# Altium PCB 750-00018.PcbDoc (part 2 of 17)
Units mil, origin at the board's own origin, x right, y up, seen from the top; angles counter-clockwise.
Board outline 7086.64 x 6299.21 mil, 8 copper layers (Top Layer, L2, L3, L4, L5, L6, L7, Bottom Layer), stack 60.6 mil thick; 1356 components, 1054 nets, 4851 pads, 4296 vias.
Unrouted connection lines stored in the file: 12.
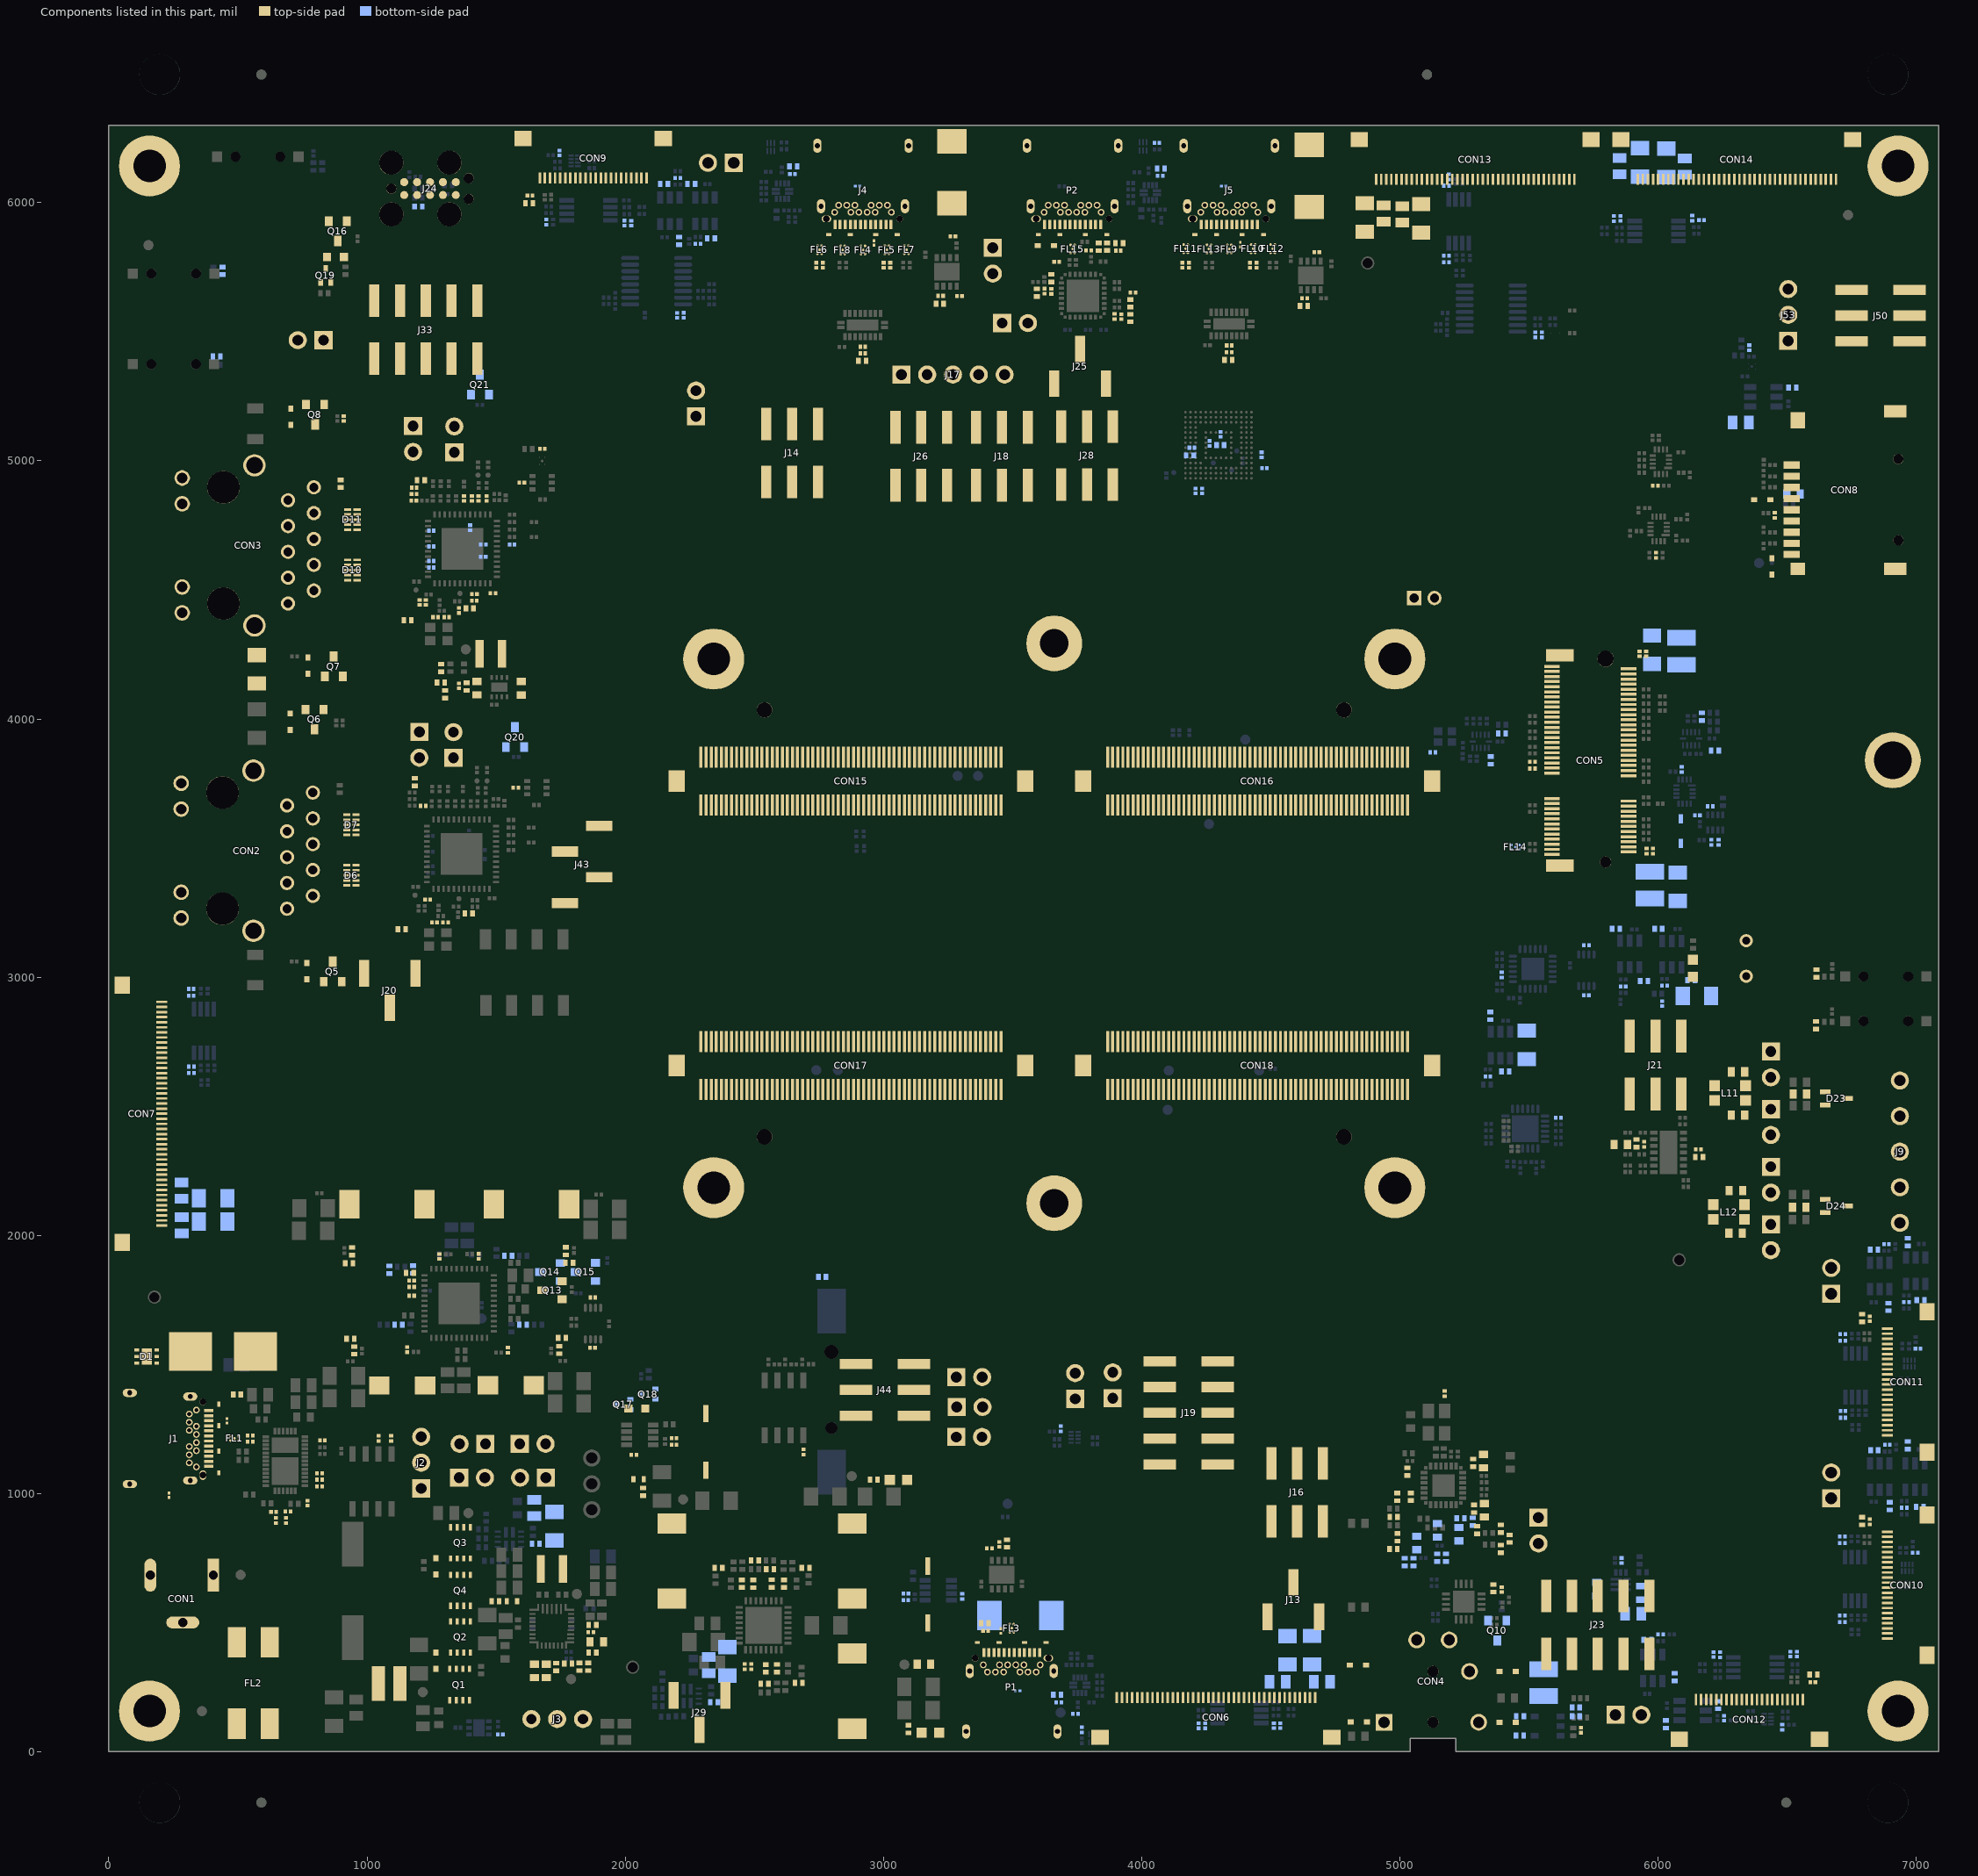
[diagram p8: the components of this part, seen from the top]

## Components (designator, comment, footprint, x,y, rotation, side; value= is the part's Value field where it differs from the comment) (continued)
C142 "0201, 27pF, 25V" "Cap, C0201, Height 0.3mm" 1261.1,3212.51 r180 top value=27pF
C143 "0201, 33pF, 25V" "Cap, C0201, Height 0.3mm" 1304.13,3212.39 r180 top value=33pF
C144 "0201, 1uF, 10V" "Cap, C0201, Height 0.3mm" 1356.39,4420.54 r90 top value=1uF
C145 "0201, 1uF, 10V" "Cap, C0201, Height 0.3mm" 1399.27,4740.79 r90 bottom value=1uF
C146 "0201, 0.1uF, 10V" "Cap, C0201, Height 0.3mm" 1415.53,4457.99 r0 top value=100nF
C147 "0201, 1000pF, 25V" "Cap, C0201, Height 0.3mm" 1449.6,4627.97 r180 bottom value=1000pF
C148 "0201, 100pF, 50V" "Cap, C0201, Height 0.3mm" 1415.74,4483.92 r0 top value=100pF
C149 "0201, 22pF, 50V" "Cap, C0201, Height 0.3mm" 1561.73,4675.3 r180 bottom value=22pF
C150 "0201, 470pF, 25V" "Cap, C0201, Height 0.3mm" 1463.05,4854.3 r90 top value=470pF
C151 "0201, 470pF, 25V" "Cap, C0201, Height 0.3mm" 1431.72,4854.3 r90 top value=470pF
C152 "0201, 1uF, 10V" "Cap, C0201, Height 0.3mm" 1182.19,4896.04 r0 top value=1uF
C153 "0201, 0.1uF, 10V" "Cap, C0201, Height 0.3mm" 1203.49,4451.48 r270 top value=100nF
C154 "0201, 1000pF, 25V" "Cap, C0201, Height 0.3mm" 1182.03,4870.97 r180 top value=1000pF
C155 "0201, 100pF, 50V" "Cap, C0201, Height 0.3mm" 1227.55,4451.46 r270 top value=100pF
C156 "0201, 100pF, 50V" "Cap, C0201, Height 0.3mm" 1181.19,4846.01 r180 top value=100pF
C157 "0201, 1uF, 10V" "Cap, C0201, Height 0.3mm" 1248.68,4729.23 r180 bottom value=1uF
C158 "0201, 1000pF, 25V" "Cap, C0201, Height 0.3mm" 1248.68,4612.08 r0 bottom value=1000pF
C159 "0201, 1000pF, 25V" "Cap, C0201, Height 0.3mm" 1248.68,4586.71 r0 bottom value=1000pF
C160 "0201, 1uF, 10V" "Cap, C0201, Height 0.3mm" 1487.6,4487.51 r180 top value=1uF
C161 "0201, 0.1uF, 10V" "Cap, C0201, Height 0.3mm" 1450.19,4675.31 r180 bottom value=100nF
C162 "0201, 1000pF, 25V" "Cap, C0201, Height 0.3mm" 1406.07,4854.3 r90 top value=1000pF
C163 "0201, 1000pF, 25V" "Cap, C0201, Height 0.3mm" 1248.67,4668.17 r0 bottom value=1000pF
C164 "0402, 220nF, 16V" "Chip. 0402, RF" 897.51,4911.38 r270 top value=220nF
C165 "0201, 10nF, 10V" "Cap, C0201, Height 0.3mm" 1375.37,4854.3 r90 top value=10nF
C166 "1206, 1000pF, 2kV" "CAP, 1206, 1.8mm, HD" 572.62,4192.66 r270 top value=1000pF
C167 "0201, 1uF, 10V" "Cap, C0201, Height 0.3mm" 909.63,5163.77 r90 top value=1uF
C168 "0201, 27pF, 25V" "Cap, C0201, Height 0.3mm" 1265.41,4394.48 r180 top value=27pF
C169 "0201, 33pF, 25V" "Cap, C0201, Height 0.3mm" 1308.07,4394.71 r180 top value=33pF
C170 "7343, 150uF, 16V" "CAP, 7343, Polarized, 2.8mm" 3530.22,527.87 r0 bottom value=150uF
C171 "0201, 0.1uF, 10V" "Cap, C0201, Height 0.3mm" 3395.57,468.29 r180 top value=100nF
C172 "0402, 10uF, 10V" "Chip. 0402, RF" 3479.01,806.58 r270 top value=10uF
C173 "0201, 0.1uF, 10V" "Cap, C0201, Height 0.3mm" 3449.09,803.37 r90 top value=100nF
C174 "0201, 0.1uF, 10V" "Cap, C0201, Height 0.3mm" 3268.73,5868.81 r180 top value=100nF
C175 "7343, 150uF, 16V" "CAP, 7343, Polarized, 2.8mm" 3264.97,6117.56 r90 top value=150uF
C176 "0402, 10uF, 10V" "Chip. 0402, RF" 2650.49,6140.43 r180 bottom value=10uF
C177 "0201, 0.1uF, 10V" "Cap, C0201, Height 0.3mm" 2647.54,6110.74 r0 bottom value=100nF
C178 "0402, 10uF, 10V" "Chip. 0402, RF" 3218.28,5608.48 r0 top value=10uF
C179 "0201, 0.1uF, 10V" "Cap, C0201, Height 0.3mm" 3221.2,5638.83 r180 top value=100nF
C180 "0201, 10nF, 10V" "Cap, C0201, Height 0.3mm" 2919.94,5441.5 r180 top value=10nF
C181 "0201, 0.1uF, 10V" "Cap, C0201, Height 0.3mm" 2920.05,5416.19 r0 top value=100nF
C182 "0402, 10uF, 10V" "Chip. 0402, RF" 2917.95,5387.18 r0 top value=10uF
C183 "0201, 0.1uF, 10V" "Cap, C0201, Height 0.3mm" 4678.08,5808.21 r180 top value=100nF
C184 "7343, 150uF, 16V" "CAP, 7343, Polarized, 2.8mm" 4649.21,6103.61 r90 top value=150uF
C185 "0402, 10uF, 10V" "Chip. 0402, RF" 4074.22,6132.67 r180 bottom value=10uF
C186 "0201, 0.1uF, 10V" "Cap, C0201, Height 0.3mm" 4071.8,6103.5 r0 bottom value=100nF
C187 "0402, 10uF, 10V" "Chip. 0402, RF" 4628.09,5599.47 r0 top value=10uF
C188 "0201, 0.1uF, 10V" "Cap, C0201, Height 0.3mm" 4630.92,5629.62 r180 top value=100nF
C189 "0201, 10nF, 10V" "Cap, C0201, Height 0.3mm" 4338.96,5446.95 r180 top value=10nF
C190 "0201, 0.1uF, 10V" "Cap, C0201, Height 0.3mm" 4338.28,5420.91 r0 top value=100nF
C191 "0402, 10uF, 10V" "Chip. 0402, RF" 4335.77,5390.66 r0 top value=10uF
C192 "0603, 10uF, 25V" "Chip, 0603, RF" 5228.02,842.55 r90 bottom value=10uF
C193 "0402, 100nF, 50V" "Chip. 0402, RF" 5235.12,903.79 r0 bottom value=100nF
C194 "0402, 1.0uF, 16V" "Chip. 0402, RF" 5281.67,891.18 r270 bottom value=1.0uF
C195 "0603, 10uF, 25V" "Chip, 0603, RF" 5326.44,935.66 r90 top value=10uF
C196 "0402, 100nF, 50V" "Chip. 0402, RF" 5286.87,941.36 r270 top value=100nF
C197 "0402, 1.0uF, 16V" "Chip. 0402, RF" 5361.65,633.11 r90 top value=1.0uF
C198 "0201, 0.1uF, 10V" "Cap, C0201, Height 0.3mm" 5394.19,627.98 r90 top value=100nF
C199 "0603, 10uF, 25V" "Chip, 0603, RF" 5323.69,1125.57 r270 top value=10uF
C200 "0402, 100nF, 50V" "Chip. 0402, RF" 5284.51,1119.05 r90 top value=100nF
C201 "0402, 220pF, 50V" "Chip. 0402, RF" 5178.91,751.86 r90 bottom value=220pF
C202 "0603, 47uF, 6.3V" "Chip, 0603, RF" 5144.76,857.54 r270 bottom value=47uF
C203 "0603, 47uF, 6.3V" "Chip, 0603, RF" 5065.31,808.86 r270 bottom value=47uF
C204 "0402, 220pF, 50V" "Chip. 0402, RF" 5017.95,734.9 r270 bottom value=220pF
C205 "1210, 100uF, 16V" "CAP, 1210, 2.8mm" 5556.18,267.56 r270 bottom value=100uF
C206 "0402, 1.0uF, 16V" "Chip. 0402, RF" 5681.57,171.42 r180 bottom value=1.0uF
C207 "0402, 2.2uF, 10V" "Chip. 0402, RF" 5464.98,137.9 r0 bottom value=2.2uF
C208 "0402, 1.0uF, 16V" "Chip. 0402, RF" 5028.45,1084.99 r90 top value=1.0uF
C209 "0402, 15pF, 50V" "Chip. 0402, RF" 4975.85,909.31 r180 top value=15pF
C210 "0402, 100nF, 50V" "Chip. 0402, RF" 5681.57,137.75 r180 bottom value=100nF
C211 "0402, 15pF, 50V" "Chip. 0402, RF" 5390.18,785.59 r270 top value=15pF
C212 "0402, 10uF, 6.3V" "Chip. 0402, RF" 4990.14,987.46 r270 top value=10uF
C213 "0402, 15pF, 50V" "Chip. 0402, RF" 5424.25,825.43 r90 top value=15pF
C214 "0402, 15pF, 50V" "Chip. 0402, RF" 5390.2,864.07 r90 top value=15pF
C215 "0805, 1uF, 50V" "CAP, 0805, 1.45mm, HD" 281.69,2173.6 r90 bottom value=1uF
C216 "1206, 10uF, 50V" "CAP, 1206, 1.8mm, HD" 403.81,2143.68 r0 bottom value=10uF
C217 "0805, 1uF, 50V" "CAP, 0805, 1.45mm, HD" 282.05,2038.71 r270 bottom value=1uF
C218 "1206, 10uF, 50V" "CAP, 1206, 1.8mm, HD" 403.55,2053.43 r0 bottom value=10uF
C219 "0805, 1uF, 50V" "CAP, 0805, 1.45mm, HD" 4526.76,270.5 r180 bottom value=1uF
C220 "0402, 4.7uF, 10V" "Chip. 0402, RF" 6158.69,2303.34 r0 top value=4.7uF
C221 "0402, 4.7uF, 10V" "Chip. 0402, RF" 2762.57,1840.06 r0 bottom value=4.7uF
C222 "0201, 0.1uF, 10V" "Cap, C0201, Height 0.3mm" 5946.16,2352.79 r90 top value=100nF
C223 "0201, 1uF, 10V" "Cap, C0201, Height 0.3mm" 4219.98,100.77 r270 bottom value=1uF
C224 "0201, 1uF, 10V" "Cap, C0201, Height 0.3mm" 5550.11,5488.24 r270 bottom value=1uF
C225 "0201, 1uF, 10V" "Cap, C0201, Height 0.3mm" 4537.13,101.02 r90 bottom value=1uF
C226 "0201, 0.1uF, 10V" "Cap, C0201, Height 0.3mm" 4245.94,100.78 r90 bottom value=100nF
C227 "0201, 0.1uF, 10V" "Cap, C0201, Height 0.3mm" 5524.13,5488.23 r90 bottom value=100nF
C228 "0201, 0.1uF, 10V" "Cap, C0201, Height 0.3mm" 4511.71,101.03 r270 bottom value=100nF
C229 "0201, 0.1uF, 10V" "Cap, C0201, Height 0.3mm" 1997.21,5920.6 r270 bottom value=100nF
C230 "0201, 1uF, 10V" "Cap, C0201, Height 0.3mm" 2201.02,5563.53 r270 bottom value=1uF
C231 "0402, 100nF, 50V" "Chip. 0402, RF" 5395.08,3944.56 r0 bottom value=100nF
C232 "0402, 100nF, 50V" "Chip. 0402, RF" 5352.33,3840.03 r270 bottom value=100nF
C233 "0402, 100nF, 50V" "Chip. 0402, RF" 6169.17,4008.89 r90 bottom value=100nF
C234 "0402, 100nF, 50V" "Chip. 0402, RF" 6219.95,3877.85 r0 bottom value=100nF
C235 "0201, 1uF, 10V" "Cap, C0201, Height 0.3mm" 6151.89,3626.7 r0 bottom value=1uF
C236 "0201, 1uF, 10V" "Cap, C0201, Height 0.3mm" 6206.42,3522.19 r90 bottom value=1uF
C237 "0201, 1uF, 10V" "Cap, C0201, Height 0.3mm" 6233.96,3522.24 r90 bottom value=1uF
C238 "0201, 1uF, 10V" "Cap, C0201, Height 0.3mm" 6201.68,3661.94 r0 bottom value=1uF
C239 "1210, 100uF, 16V" "CAP, 1210, 2.8mm" 6089.87,4262.22 r270 bottom value=100uF
C240 "1206, 10uF, 50V" "CAP, 1206, 1.8mm, HD" 5976.56,4268.25 r270 bottom value=10uF
C241 "0201, 0.1uF, 10V" "Cap, C0201, Height 0.3mm" 5927.93,4252.79 r270 top value=100nF
C242 "0201, 0.1uF, 10V" "Cap, C0201, Height 0.3mm" 5953.74,4252.66 r270 top value=100nF
C243 "Radial Can, 220uF, 25V" "CAP, CAPAE, 8mm Dia." 6341.2,3072.47 r270 top value=220uF
C244 "1206, 22uF, 10V" "CAP, 1206, 1.8mm, HD" 6150.53,2927.5 r0 bottom value=22uF
C245 "0402, 100nF, 50V" "Chip. 0402, RF" 6128.53,2988.72 r0 bottom value=100nF
C246 "0402, 1.0nF, 50V" "Chip. 0402, RF" 6001.09,3187.06 r180 bottom value=1.0nF
C247 "0201, 1000pF, 25V" "Cap, C0201, Height 0.3mm" 6024.8,2967.25 r0 bottom value=1000pF
C248 "0201, 0.1uF, 10V" "Cap, C0201, Height 0.3mm" 5513.23,3833.85 r180 top value=100nF
C249 "0201, 0.1uF, 10V" "Cap, C0201, Height 0.3mm" 5513.23,3808.18 r180 top value=100nF
C250 "1210, 100uF, 16V" "CAP, 1210, 2.8mm" 5967.31,3356.77 r90 bottom value=100uF
C251 "1206, 10uF, 50V" "CAP, 1206, 1.8mm, HD" 6076.31,3350.26 r90 bottom value=10uF
C252 "0201, 0.1uF, 10V" "Cap, C0201, Height 0.3mm" 5980.05,3488.47 r270 top value=100nF
C253 "0201, 0.1uF, 10V" "Cap, C0201, Height 0.3mm" 5955.34,3488.47 r270 top value=100nF
C254 "0402, 4.7uF, 10V" "Chip. 0402, RF" 5916.39,2356.75 r90 top value=4.7uF
C255 "0201, 0.1uF, 10V" "Cap, C0201, Height 0.3mm" 6155.62,2332.89 r0 top value=100nF
C256 "0201, 0.1uF, 10V" "Cap, C0201, Height 0.3mm" 6996.04,770.51 r180 bottom value=100nF
C257 "0201, 0.1uF, 10V" "Cap, C0201, Height 0.3mm" 1745.35,6192.37 r270 bottom value=100nF
C258 "0201, 0.1uF, 10V" "Cap, C0201, Height 0.3mm" 6480.61,95.49 r90 bottom value=100nF
C259 "0201, 0.1uF, 10V" "Cap, C0201, Height 0.3mm" 7006.26,1561.86 r180 bottom value=100nF
C260 "0201, 0.1uF, 10V" "Cap, C0201, Height 0.3mm" 3686.64,1251.1 r270 bottom value=100nF
C261 "0201, 0.1uF, 10V" "Cap, C0201, Height 0.3mm" 5173.46,1387.28 r270 top value=100nF
C262 "0201, 0.1uF, 10V" "Cap, C0201, Height 0.3mm" 6353.08,5437.83 r90 bottom value=100nF
C263 "0201, 0.1uF, 10V" "Cap, C0201, Height 0.3mm" 1575.91,3734.28 r180 top value=100nF
C264 "0603, 4.7nF, 50V" "Chip, 0603, RF" 6548.73,2548.11 r180 top value=4.7nF
C265 "0603, 100pF, 50V" "Chip, 0603, RF" 6308.96,2633.34 r180 top value=100pF
C266 "0603, 100pF, 50V" "Chip, 0603, RF" 6308.96,2466.38 r180 top value=100pF
C267 "0201, 0.1uF, 10V" "Cap, C0201, Height 0.3mm" 1599.2,4915.1 r180 top value=100nF
C268 "0201, 0.1uF, 10V" "Cap, C0201, Height 0.3mm" 5701.21,83.6 r270 top value=100nF
C269 "0201, 0.1uF, 10V" "Cap, C0201, Height 0.3mm" 1678.8,5046.2 r0 top value=100nF
C270 "0201, 47nF, 10V" "Cap, C0201, Height 0.3mm" 1515.99,67.28 r180 bottom value=47nF
C271 "0402, 10uF, 10V" "Chip. 0402, RF" 3672.72,220.74 r0 bottom value=10uF
C272 "0201, 0.1uF, 10V" "Cap, C0201, Height 0.3mm" 3679.17,191.12 r180 bottom value=100nF
C273 "0402, 10uF, 10V" "Chip. 0402, RF" 3912.82,5843.73 r0 top value=10uF
C274 "0201, 0.1uF, 10V" "Cap, C0201, Height 0.3mm" 3909.4,5814.1 r0 top value=100nF
C275 "0201, 0.1uF, 10V" "Cap, C0201, Height 0.3mm" 4059.08,6230.96 r0 bottom value=100nF
C276 "0402, 10uF, 6.3V" "Chip. 0402, RF" 5041.72,987.68 r270 top value=10uF
C277 "0603, 4.7nF, 50V" "Chip, 0603, RF" 6546.49,2109.45 r180 top value=4.7nF
C278 "0603, 100pF, 50V" "Chip, 0603, RF" 6301.25,2173.61 r180 top value=100pF
C279 "0603, 100pF, 50V" "Chip, 0603, RF" 6300.16,2008.1 r180 top value=100pF
C280 "0201, 0.1uF, 10V" "Cap, C0201, Height 0.3mm" 3670.81,5770.42 r0 top value=100nF
C281 "0402, 10uF, 10V" "Chip. 0402, RF" 3650.56,5707.29 r90 top value=10uF
C282 "0201, 0.1uF, 10V" "Cap, C0201, Height 0.3mm" 3794.63,5814.65 r180 top value=100nF
C283 "0402, 10uF, 10V" "Chip. 0402, RF" 3832.92,5829.2 r90 top value=10uF
C284 "0201, 0.1uF, 10V" "Cap, C0201, Height 0.3mm" 3966.01,5651.74 r0 top value=100nF
C285 "0201, 10nF, 10V" "Cap, C0201, Height 0.3mm" 3894.9,5558.86 r90 top value=10nF
C286 "0201, 10nF, 10V" "Cap, C0201, Height 0.3mm" 3650.09,5656.45 r270 top value=10nF
C287 "0201, 0.1uF, 10V" "Cap, C0201, Height 0.3mm" 3920.59,5558.28 r270 top value=100nF
C288 "0201, 0.1uF, 10V" "Cap, C0201, Height 0.3mm" 3624.25,5657.22 r90 top value=100nF
C289 "0402, 10uF, 10V" "Chip. 0402, RF" 3956.57,5553.14 r270 top value=10uF
C290 "0402, 10uF, 10V" "Chip. 0402, RF" 3593.98,5651.1 r90 top value=10uF
C291 "0805, 22uF, 25V" "CAP, 0805, 1.45mm, HD" 5903.51,534.71 r0 bottom value=22uF
C292 "0603, 10uF, 25V" "Chip, 0603, RF" 5762.49,629.83 r90 bottom value=10uF
C293 "0402, 22pF, 50V" "Chip. 0402, RF" 1178.17,1868.12 r270 bottom value=22pF
C294 "0201, 0.1uF, 10V" "Cap, C0201, Height 0.3mm" 5991.82,4634.22 r90 top value=100nF
C295 "0201, 0.1uF, 10V" "Cap, C0201, Height 0.3mm" 5988.92,4903.46 r0 top value=100nF
C296 "0201, 10pF, 25V" "Cap, C0201, Height 0.3mm" 6451.59,4788.66 r270 top value=10pF
C297 "0603, 100nF, 50V" "Chip, 0603, RF" 6524.38,4871.2 r0 bottom value=100nF
C298 "0805, 22uF, 25V" "CAP, 0805, 1.45mm, HD" 6320.31,5148.9 r180 bottom value=22uF
C299 "0402, 1.0nF, 50V" "Chip. 0402, RF" 6519.97,5283.79 r0 bottom value=1.0nF
C300 "0402, 100nF, 50V" "Chip. 0402, RF" 1198.8,5984.85 r180 bottom value=100nF
C301 "0201, 1uF, 10V" "Cap, C0201, Height 0.3mm" 1694.63,5924.2 r270 bottom value=1uF
C302 "0201, 0.1uF, 10V" "Cap, C0201, Height 0.3mm" 5394.49,3009.04 r270 bottom value=100nF
C303 "0402, 15pF, 50V" "Chip. 0402, RF" 4974.94,785.64 r180 top value=15pF
C304 "0402, 100nF, 50V" "Chip. 0402, RF" 417.27,5404.84 r180 bottom value=100nF
C305 "0603, 10uF, 25V" "Chip, 0603, RF" 1597.86,4119.12 r90 top value=10uF
C306 "0402, 22pF, 50V" "Chip. 0402, RF" 1287.05,4197.73 r90 top value=22pF
C307 "0603, 10uF, 25V" "Chip, 0603, RF" 1426,4119.62 r270 top value=10uF
C308 "0402, 4.7uF, 10V" "Chip. 0402, RF" 1386.31,4125.49 r270 top value=4.7uF
C309 "0201, 0.1uF, 10V" "Cap, C0201, Height 0.3mm" 1355.47,4128.6 r270 top value=100nF
C310 "0402, 10uF, 10V" "Chip. 0402, RF" 4187.08,5020.93 r0 bottom value=10uF
C311 "1206, 22uF, 10V" "CAP, 1206, 1.8mm, HD" 5491.59,2737.84 r90 bottom value=22uF
C312 "0201, 0.1uF, 10V" "Cap, C0201, Height 0.3mm" 3000.55,5757.42 r90 top value=100nF
C313 "0201, 0.1uF, 10V" "Cap, C0201, Height 0.3mm" 3026.14,5757.42 r90 top value=100nF
C314 "0201, 0.1uF, 10V" "Cap, C0201, Height 0.3mm" 2739.73,5757.42 r90 top value=100nF
C315 "0201, 0.1uF, 10V" "Cap, C0201, Height 0.3mm" 2765.5,5757.42 r90 top value=100nF
C316 "0201, 0.1uF, 10V" "Cap, C0201, Height 0.3mm" 4419.4,5757.42 r90 top value=100nF
C317 "0201, 0.1uF, 10V" "Cap, C0201, Height 0.3mm" 4444.88,5757.42 r90 top value=100nF
C318 "0201, 0.1uF, 10V" "Cap, C0201, Height 0.3mm" 4157.51,5757.42 r90 top value=100nF
C319 "0201, 0.1uF, 10V" "Cap, C0201, Height 0.3mm" 4183.18,5757.42 r90 top value=100nF
C320 "0201, 0.1uF, 10V" "Cap, C0201, Height 0.3mm" 5127.12,3870.85 r0 bottom value=100nF
C321 "0402, 100nF, 50V" "Chip. 0402, RF" 5945.25,2985.85 r0 bottom value=100nF
C322 "0201, 0.1uF, 10V" "Cap, C0201, Height 0.3mm" 1630.81,6027.52 r0 top value=100nF
C323 "0402, 10uF, 10V" "Chip. 0402, RF" 1627.85,5997.73 r0 top value=10uF
C324 "0201, 0.1uF, 10V" "Cap, C0201, Height 0.3mm" 6820.06,890.99 r270 top value=100nF
C325 "0402, 10uF, 10V" "Chip. 0402, RF" 6790.41,893.68 r270 top value=10uF
C326 "0201, 1000pF, 25V" "Cap, C0201, Height 0.3mm" 5858.44,740.56 r90 bottom value=1000pF
C327 "0402, 100nF, 50V" "Chip. 0402, RF" 2331.99,5862.38 r180 bottom value=100nF
C328 "0402, 100nF, 50V" "Chip. 0402, RF" 6837.54,1167.19 r0 bottom value=100nF
C329 "0402, 1.0nF, 50V" "Chip. 0402, RF" 2255.82,6073.02 r180 bottom value=1.0nF
C330 "0402, 1.0nF, 50V" "Chip. 0402, RF" 6896.94,951.56 r270 bottom value=1.0nF
C331 "0201, 1000pF, 25V" "Cap, C0201, Height 0.3mm" 2281.78,5840.89 r0 bottom value=1000pF
C332 "0201, 1000pF, 25V" "Cap, C0201, Height 0.3mm" 6887.61,1188.75 r180 bottom value=1000pF
C333 "0402, 100nF, 50V" "Chip. 0402, RF" 2150.24,6072.5 r0 bottom value=100nF
C334 "0402, 100nF, 50V" "Chip. 0402, RF" 7013.57,949.04 r180 bottom value=100nF
C335 "0402, 1.0nF, 50V" "Chip. 0402, RF" 2208.75,5851.88 r270 bottom value=1.0nF
C336 "0201, 0.1uF, 10V" "Cap, C0201, Height 0.3mm" 6820.2,1677.14 r270 top value=100nF
C337 "0402, 10uF, 10V" "Chip. 0402, RF" 6790.41,1680.1 r270 top value=10uF
C338 "0201, 0.1uF, 10V" "Cap, C0201, Height 0.3mm" 6599,269.79 r180 top value=100nF
C339 "0402, 10uF, 10V" "Chip. 0402, RF" 6601.68,299.43 r180 top value=10uF
C340 "0402, 1.0nF, 50V" "Chip. 0402, RF" 6966.18,1187.09 r90 bottom value=1.0nF
C341 "0201, 1000pF, 25V" "Cap, C0201, Height 0.3mm" 2203.24,6094.96 r180 bottom value=1000pF
C342 "0201, 1000pF, 25V" "Cap, C0201, Height 0.3mm" 6953.47,945.14 r180 bottom value=1000pF
C343 "0402, 100nF, 50V" "Chip. 0402, RF" 5959.28,433.4 r0 bottom value=100nF
C344 "0402, 100nF, 50V" "Chip. 0402, RF" 6836.04,1945.11 r0 bottom value=100nF
C345 "0402, 1.0nF, 50V" "Chip. 0402, RF" 6064.12,289.3 r90 bottom value=1.0nF
C346 "0402, 1.0nF, 50V" "Chip. 0402, RF" 6892.76,1722.91 r270 bottom value=1.0nF
C347 "0201, 1000pF, 25V" "Cap, C0201, Height 0.3mm" 6009.55,454.24 r180 bottom value=1000pF
C348 "0201, 1000pF, 25V" "Cap, C0201, Height 0.3mm" 6884.51,1966.19 r180 bottom value=1000pF
C349 "0402, 100nF, 50V" "Chip. 0402, RF" 7016.48,1748.61 r180 bottom value=100nF
C350 "0402, 100nF, 50V" "Chip. 0402, RF" 6232.67,181.02 r270 bottom value=100nF
C351 "0402, 1.0nF, 50V" "Chip. 0402, RF" 6966.57,1974.1 r90 bottom value=1.0nF
C352 "0402, 1.0nF, 50V" "Chip. 0402, RF" 6030.54,106.46 r270 bottom value=1.0nF
C353 "0402, 4.7uF, 10V" "Chip. 0402, RF" 4304.53,5061.65 r0 bottom value=4.7uF
C354 "0201, 220nF, 10V" "Cap, C0201, Height 0.3mm" 4262.77,5067.17 r90 bottom value=220nF
C355 "0201, 220nF, 10V" "Cap, C0201, Height 0.3mm" 4305.52,5102.38 r90 bottom value=220nF
C356 "0402, 100nF, 50V" "Chip. 0402, RF" 5408.52,2635.61 r180 bottom value=100nF
C357 "0201, 220nF, 10V" "Cap, C0201, Height 0.3mm" 4194.47,5050.56 r180 bottom value=220nF
C358 "0201, 220nF, 10V" "Cap, C0201, Height 0.3mm" 4475.56,4971.39 r0 bottom value=220nF
C359 "0201, 220nF, 10V" "Cap, C0201, Height 0.3mm" 4464.23,5022.9 r90 bottom value=220nF
C360 "0201, 220nF, 10V" "Cap, C0201, Height 0.3mm" 4233.98,4883.09 r270 bottom value=220nF
C361 "0201, 1uF, 10V" "Cap, C0201, Height 0.3mm" 4207.98,4883.25 r270 bottom value=1uF
C362 "0201, 1000pF, 25V" "Cap, C0201, Height 0.3mm" 6961.39,1742.09 r180 bottom value=1000pF
C363 "0201, 1000pF, 25V" "Cap, C0201, Height 0.3mm" 6255.48,129.96 r90 bottom value=1000pF
C364 "0402, 100nF, 50V" "Chip. 0402, RF" 6612.78,3014.77 r90 top value=100nF
C365 "0402, 100nF, 50V" "Chip. 0402, RF" 6611.91,2814.1 r270 top value=100nF
C366 "0402, 100nF, 50V" "Chip. 0402, RF" 439.61,5735.8 r270 bottom value=100nF
C367 "0201, 0.1uF, 10V" "Cap, C0201, Height 0.3mm" 5722.46,3124.06 r180 bottom value=100nF
C368 "0201, 0.1uF, 10V" "Cap, C0201, Height 0.3mm" 5721.9,2930.16 r0 bottom value=100nF
C369 "0402, 10nF, 50V" "Chip. 0402, RF" 5464.17,63.24 r0 bottom value=10nF
C370 "0402, 1.0nF, 50V" "Chip. 0402, RF" 5836.89,3187.8 r180 bottom value=1.0nF
C371 "0201, 1000pF, 25V" "Cap, C0201, Height 0.3mm" 5864.64,2964.48 r0 bottom value=1000pF
C372 "0402, 1.0nF, 50V" "Chip. 0402, RF" 5350.43,2850.73 r90 bottom value=1.0nF
C373 "0201, 1000pF, 25V" "Cap, C0201, Height 0.3mm" 5340.79,2615.27 r180 bottom value=1000pF
C374 "0201, 0.1uF, 10V" "Cap, C0201, Height 0.3mm" 1874.27,1759.58 r0 top value=100nF
C375 "0201, 0.1uF, 10V" "Cap, C0201, Height 0.3mm" 1873.08,1564.35 r180 top value=100nF
C376 "1206, 10uF, 50V" "CAP, 1206, 1.8mm, HD" 4564.13,392.96 r90 bottom value=10uF
C377 "0805, 1uF, 50V" "CAP, 0805, 1.45mm, HD" 5008.58,5953.68 r270 top value=1uF
C378 "1206, 10uF, 50V" "CAP, 1206, 1.8mm, HD" 5082.32,5939.14 r270 top value=10uF
C379 "0805, 1uF, 50V" "CAP, 0805, 1.45mm, HD" 6103.28,6139.25 r90 bottom value=1uF
C380 "1206, 10uF, 50V" "CAP, 1206, 1.8mm, HD" 6031.7,6154.02 r90 bottom value=10uF
C381 "0805, 1uF, 50V" "CAP, 0805, 1.45mm, HD" 4697.6,271.31 r0 bottom value=1uF
C382 "1206, 10uF, 50V" "CAP, 1206, 1.8mm, HD" 4659.46,393.63 r90 bottom value=10uF
C383 "0805, 1uF, 50V" "CAP, 0805, 1.45mm, HD" 4937.03,5957 r270 top value=1uF
C384 "1206, 10uF, 50V" "CAP, 1206, 1.8mm, HD" 4863.82,5942.11 r270 top value=10uF
C385 "0805, 1uF, 50V" "CAP, 0805, 1.45mm, HD" 5850.83,6141.01 r90 bottom value=1uF
C386 "1206, 10uF, 50V" "CAP, 1206, 1.8mm, HD" 5929.66,6155.78 r90 bottom value=10uF
C387 "0201, 0.1uF, 10V" "Cap, C0201, Height 0.3mm" 5613.54,2455.68 r0 bottom value=100nF
C388 "0402, 4.7nF, 25V" "Chip. 0402, RF" 1085.88,1866.79 r90 bottom value=4.7nF
C389 "0402, 4.7nF, 25V" "Chip. 0402, RF" 1165.61,1854.7 r180 top value=4.7nF
C390 "0201, 1uF, 10V" "Cap, C0201, Height 0.3mm" 2023.27,5920.46 r90 bottom value=1uF
C391 "0201, 0.1uF, 10V" "Cap, C0201, Height 0.3mm" 2226.69,5563.52 r90 bottom value=100nF
C392 "0201, 0.1uF, 10V" "Cap, C0201, Height 0.3mm" 6715.11,1591.99 r0 bottom value=100nF
C393 "0201, 0.1uF, 10V" "Cap, C0201, Height 0.3mm" 2689.82,1161.14 r270 top value=100nF
C394 "0201, 0.1uF, 10V" "Cap, C0201, Height 0.3mm" 6716.17,1320.16 r180 bottom value=100nF
C395 "0201, 1uF, 10V" "Cap, C0201, Height 0.3mm" 6715.31,1617.38 r180 bottom value=1uF
C396 "0201, 1uF, 10V" "Cap, C0201, Height 0.3mm" 6716.17,1293.51 r0 bottom value=1uF
C397 "0201, 0.1uF, 10V" "Cap, C0201, Height 0.3mm" 6713.58,807.93 r0 bottom value=100nF
C398 "0201, 0.1uF, 10V" "Cap, C0201, Height 0.3mm" 6713.5,527.32 r180 bottom value=100nF
C399 "0201, 1uF, 10V" "Cap, C0201, Height 0.3mm" 6713.44,833.57 r180 bottom value=1uF
C400 "0201, 1uF, 10V" "Cap, C0201, Height 0.3mm" 6713.54,501.88 r0 bottom value=1uF
C401 "0201, 0.1uF, 10V" "Cap, C0201, Height 0.3mm" 6512.31,378 r270 bottom value=100nF
C402 "0201, 0.1uF, 10V" "Cap, C0201, Height 0.3mm" 6239.98,375.98 r90 bottom value=100nF
C403 "0201, 1uF, 10V" "Cap, C0201, Height 0.3mm" 6538.09,378 r90 bottom value=1uF
C404 "0201, 1uF, 10V" "Cap, C0201, Height 0.3mm" 6214.09,376.29 r270 bottom value=1uF
C405 "0201, 0.1uF, 10V" "Cap, C0201, Height 0.3mm" 5180.14,6065.49 r0 bottom value=100nF
C406 "0201, 0.1uF, 10V" "Cap, C0201, Height 0.3mm" 5180.29,5794.36 r180 bottom value=100nF
C407 "0201, 1uF, 10V" "Cap, C0201, Height 0.3mm" 5189.09,6099.52 r90 bottom value=1uF
C408 "0201, 1uF, 10V" "Cap, C0201, Height 0.3mm" 5180.1,5769.15 r0 bottom value=1uF
C409 "0201, 0.1uF, 10V" "Cap, C0201, Height 0.3mm" 6131.89,5939.78 r270 bottom value=100nF
C410 "0201, 0.1uF, 10V" "Cap, C0201, Height 0.3mm" 5854.61,5938.79 r90 bottom value=100nF
C411 "0201, 1uF, 10V" "Cap, C0201, Height 0.3mm" 6168.33,5932.14 r0 bottom value=1uF
C412 "0201, 1uF, 10V" "Cap, C0201, Height 0.3mm" 5828.47,5938.49 r270 bottom value=1uF
C413 "0201, 0.1uF, 10V" "Cap, C0201, Height 0.3mm" 318.79,2928.81 r0 bottom value=100nF
C414 "0201, 0.1uF, 10V" "Cap, C0201, Height 0.3mm" 319.33,2653.91 r180 bottom value=100nF
C415 "0201, 1uF, 10V" "Cap, C0201, Height 0.3mm" 318.66,2954.71 r180 bottom value=1uF
C416 "0201, 1uF, 10V" "Cap, C0201, Height 0.3mm" 319.33,2628.55 r0 bottom value=1uF
C417 "0402, 0.1uF, 25V" "Chip. 0402, RF" 1653.35,805.19 r0 bottom value=0.1uF
C418 "0402, 0.1uF, 25V" "Chip. 0402, RF" 2343.93,192.4 r0 bottom value=0.1uF
C419 "0805, 1uF, 25V" "CAP, 0805, 1.45mm, HD" 1647.18,944.65 r90 bottom value=1uF
C420 "1206, 10uF, 25V" "CAP, 1206, 1.8mm, HD" 1725.75,873.73 r270 bottom value=10uF
C421 "0805, 1uF, 25V" "CAP, 0805, 1.45mm, HD" 2323.45,335.15 r90 bottom value=1uF
C422 "1206, 10uF, 25V" "CAP, 1206, 1.8mm, HD" 2394.9,350.34 r90 bottom value=10uF
C423 "0201, 100nF, 10V" "Cap, C0201, Height 0.3mm" 6091.11,3804.38 r90 bottom value=100nF
CON1 "SH, DC-005-2.0" "TOUKE, TK18-001-A" 282.49,592.27 r0 top value=DC-005-2.0
CON2 "Kingconn, 7RJ45-F0-0332" "Kingconn, 7RJ45-F0-0332" 535.08,3490 r270 top locked value=7RJ45-F0-0332
CON3 "Kingconn, 7RJ45-F0-0332" "Kingconn, 7RJ45-F0-0332" 539.02,4672.31 r270 top locked value=7RJ45-F0-0332
CON4 "CUI, SJ-43515TS" "AUDIO JACK, 3.5mm" 5127.87,273.62 r90 top locked value=3.5mm
CON5 "JAE, SM3ZS067U410AER1000" "JAE, SM3ZS067U410AER1000" 5702.6,3804.69 r270 top value=SM3ZS067U410AER1000
CON6 "Omron, XF2M-4015-1A" "Omron, XF2M-4015-1A" 4287.8,56.13 r0 top locked value=XF2M-4015-1A
CON7 "Omron, XF2M-4515-1A" "Omron, XF2M-4515-1A" 128.07,2471.28 r270 top value=XF2M-4515-1A
CON8 "Kingconn, 7MSDP-BA-1016" "Kingconn, 7MSDP-BA-1011-D" 6723.64,4886.99 r90 top locked value=7MSDP-BA-1016
CON9 "Omron, XF2M-2215-1A" "Omron, XF2M-2215-1A" 1875.69,6134.51 r180 top locked value=XF2M-2215-1A
CON10 "Omron, XF2M-2215-1A" "Omron, XF2M-2215-1A" 6927.2,645.29 r90 top locked value=XF2M-2215-1A
CON11 "Omron, XF2M-2215-1A" "Omron, XF2M-2215-1A" 6927.2,1432.26 r90 top locked value=XF2M-2215-1A
CON12 "Omron, XF2M-2215-1A" "Omron, XF2M-2215-1A" 6353.29,162.65 r0 top locked value=XF2M-2215-1A
CON13 "Omron, XF2M-4015-1A" "Omron, XF2M-4015-1A" 5291.62,6244.14 r180 top value=XF2M-4015-1A
CON14 "Omron, XF2M-4015-1A" "Omron, XF2M-4015-1A" 6305.03,6244.14 r180 top locked value=XF2M-4015-1A
CON15 "Kyocera, 145046120640868+" "Kyocera, 145046120640868+" 2874.02,3759.4 r90 top locked value=145046120640868+
CON16 "Kyocera, 145046120640868+" "Kyocera, 145046120640868+" 4448.82,3759.4 r90 top locked value=145046120640868+
CON17 "Kyocera, 145046120640868+" "Kyocera, 145046120640868+" 2874.02,2657.92 r270 top locked value=145046120640868+
CON18 "Kyocera, 145046120640868+" "Kyocera, 145046120640868+" 4448.82,2657.92 r270 top locked value=145046120640868+
D1 "TI, TVS2200DRVR" "WSON6_2x2, Height 0.8mm" 146.72,1530.92 r0 top value=TVS2200DRVR
D2 "TI, TPD1E01B04DPLT" X2SON-2#1 233.23,993.48 r270 top value=TPD1E01B04DPLT
D3 "TI, TPD1E01B04DPLT" X2SON-2#1 456.81,1281.6 r90 top value=TPD1E01B04DPLT
D4 "Diodes Inc., BZT52C12T" SOD523#1 1266.35,352.92 r90 top value=BZT52C12T
D5 "Diodes Inc., BZT52C12T" SOD523#1 1266.35,718.61 r90 top value=BZT52C12T
D6 "Nexperia, IP4292CZ10-TBR,115" DFN10L 939.3,3394.77 r0 top value=IP4292CZ10-TBR,115
D7 "Nexperia, IP4292CZ10-TBR,115" DFN10L 939.3,3589.92 r0 top value=IP4292CZ10-TBR,115
D8 "On Semiconductor, ESD5B5.0ST1G" SOD523#1 767.09,3023.98 r270 top value=ESD5B5.0ST1G
D9 "On Semiconductor, ESD5B5.0ST1G" SOD523#1 702.41,3989.85 r90 top value=ESD5B5.0ST1G
D10 "Nexperia, IP4292CZ10-TBR,115" DFN10L 943.24,4577.08 r0 top value=IP4292CZ10-TBR,115
D11 "Nexperia, IP4292CZ10-TBR,115" DFN10L 943.24,4772.24 r0 top value=IP4292CZ10-TBR,115
D12 "On Semiconductor, ESD5B5.0ST1G" SOD523#1 771.03,4206.3 r270 top value=ESD5B5.0ST1G
D13 "On Semiconductor, ESD5B5.0ST1G" SOD523#1 704.6,5170.42 r90 top value=ESD5B5.0ST1G
D14 "TI, TPD1E01B04DPLT" X2SON-2#2 2963.17,5843.64 r270 top value=TPD1E01B04DPLT
D15 "TI, TPD1E01B04DPLT" X2SON-2#2 2899.59,6063.95 r0 bottom value=TPD1E01B04DPLT
D16 "TI, TPD1E01B04DPLT" X2SON-2#2 4381.89,5837.34 r270 top value=TPD1E01B04DPLT
D17 "TI, TPD1E01B04DPLT" X2SON-2#2 4317.27,6063.95 r0 bottom value=TPD1E01B04DPLT
D18 "On Semiconductor, ESD5B5.0ST1G" SOD523#1 5417.36,113.37 r0 top value=ESD5B5.0ST1G
D19 "On Semiconductor, ESD5B5.0ST1G" SOD523#1 4838.02,335.75 r180 top value=ESD5B5.0ST1G
D20 "On Semiconductor, ESD5B5.0ST1G" SOD523#1 5416.98,311.1 r0 top value=ESD5B5.0ST1G
D21 "On Semiconductor, ESD5B5.0ST1G" SOD523#1 4840.35,115.51 r180 top value=ESD5B5.0ST1G
D22 "On Semi., NSR0320MW2T1G" SOD323 6087.55,3565.84 r270 bottom value=NSR0320MW2T1G
D23 "TI, ESD2CAN24DCKRQ1" "SC-70, 3 Leads, 2.1mm x 2.0mm, Height 1.1mm, SMD" 6690.49,2530.29 r0 top value=ESD2CAN24DCKRQ1
D24 "TI, ESD2CAN24DCKRQ1" "SC-70, 3 Leads, 2.1mm x 2.0mm, Height 1.1mm, SMD" 6690.46,2114.13 r0 top value=ESD2CAN24DCKRQ1
D25 "On Semiconductor, ESD5B5.0ST1G" SOD523#2 3629.44,5833.49 r180 top value=ESD5B5.0ST1G
D26 "TI, TPD1E01B04DPLT" X2SON-2#1 3454.6,467.74 r90 top value=TPD1E01B04DPLT
D27 "On Semiconductor, ESD5B5.0ST1G" SOD523#2 6440.88,4590.51 r270 top value=ESD5B5.0ST1G
D28 "On Semiconductor, ESD5B5.0ST1G" SOD523#2 6402.99,4849.16 r180 top value=ESD5B5.0ST1G
D29 "TI, TPD1E01B04DPLT" X2SON-2#1 3519.52,236.16 r180 bottom value=TPD1E01B04DPLT
F1 "Littelfuse, 0154010.DR" "Littlefuse, 0154010.DR" 442.05,1550.93 r0 top value=0154010.DR
FB1 "Murata, BLM15HB221SN1#" "FB, FB0402, RF" 1393.58,3246.58 r0 top value=BLM15HB221SN1
FB2 "Murata, BLM15HB221SN1#" "FB, FB0402, RF" 1184.36,3755.48 r270 top value=BLM15HB221SN1
FB3 "Murata, BLM15HB221SN1#" "FB, FB0402, RF" 1397.52,4428.89 r0 top value=BLM15HB221SN1
FB4 "Murata, BLM15HB221SN1#" "FB, FB0402, RF" 1208.63,4924.29 r180 top value=BLM15HB221SN1
FB5 "Murata, BLM15AG121SN1" "FB, FB0402, RF" 5144.76,751.69 r270 bottom value=BLM15AG121SN1
FB6 "Murata, BLM15AG121SN1" "FB, FB0402, RF" 5051.89,734.9 r270 bottom value=BLM15AG121SN1
FB8 "Murata, BLM15AG121SN1" "FB, FB0402, RF" 4990.5,830.92 r270 top value=BLM15AG121SN1
FB9 "Murata, BLM18PG221SH1#" "FB, FB0603, RF" 5855.17,2351.44 r180 top value=BLM18PG221SH1#
FB13 "Mutata, BLM15PD121SN1#" "FB, FB0402, RF" 3866.48,5829.33 r90 top value=BLM15PD121SN1
FB14 "Mutata, BLM15PD121SN1#" "FB, FB0402, RF" 3956.27,5610.05 r90 top value=BLM15PD121SN1
FB15 "Murata, BLM15HB221SN1#" "FB, FB0402, RF" 1134.26,3186.56 r180 top value=BLM15HB221SN1
FB16 "Murata, BLM15HB221SN1#" "FB, FB0402, RF" 1301.83,4095.9 r270 top value=BLM15HB221SN1
FB17 "Murata, BLM15HB221SN1#" "FB, FB0402, RF" 1156.93,4382.32 r0 top value=BLM15HB221SN1
FB18 "Murata, BLM15HB221SN1#" "FB, FB0402, RF" 1285.44,4140.51 r180 top value=BLM15HB221SN1
FL1 "Nexperia, PCMF1USB3S" "Nexperia, PCMF1USB3S"#1 486.89,1213.83 r90 top value=PCMF1USB3S
FL2 "Maglayers, MCM-9070F-701" "Maglayers, MCM-9070FH0" 559.41,266.43 r270 top value=MCM-9070F-701
FL3 "Nexperia, PCMF1USB3S" "Nexperia, PCMF1USB3S"#2 3496.61,478.52 r180 top value=PCMF1USB3S
FL4 "Nexperia, PCMF1USB3S" "Nexperia, PCMF1USB3S"#2 2920.8,5816.57 r0 top value=PCMF1USB3S
FL5 "Nexperia, PCMF1USB3S" "Nexperia, PCMF1USB3S"#2 3013.14,5817.43 r0 top value=PCMF1USB3S
FL6 "Nexperia, PCMF1USB3S" "Nexperia, PCMF1USB3S"#2 2752.36,5817.52 r0 top value=PCMF1USB3S
FL7 "Nexperia, PCMF1USB3S" "Nexperia, PCMF1USB3S"#2 3089.08,5817.52 r0 top value=PCMF1USB3S
FL8 "Nexperia, PCMF1USB3S" "Nexperia, PCMF1USB3S"#2 2842.06,5816.57 r0 top value=PCMF1USB3S
FL9 "Nexperia, PCMF1USB3S" "Nexperia, PCMF1USB3S"#2 4339.27,5820.69 r0 top value=PCMF1USB3S
FL10 "Nexperia, PCMF1USB3S" "Nexperia, PCMF1USB3S"#2 4431.61,5821.55 r0 top value=PCMF1USB3S
FL11 "Nexperia, PCMF1USB3S" "Nexperia, PCMF1USB3S"#2 4170.84,5821.63 r0 top value=PCMF1USB3S
FL12 "Nexperia, PCMF1USB3S" "Nexperia, PCMF1USB3S"#2 4507.56,5821.63 r0 top value=PCMF1USB3S
FL13 "Nexperia, PCMF1USB3S" "Nexperia, PCMF1USB3S"#2 4260.53,5820.69 r0 top value=PCMF1USB3S
FL14 "Nexperia, PCMF1USB3S" "Nexperia, PCMF1USB3S"#2 5447.72,3504.2 r90 bottom value=PCMF1USB3S
FL15 "Nexperia, PCMF1USB3S" "Nexperia, PCMF1USB3S"#2 3732.58,5820.69 r0 top value=PCMF1USB3S
J1 "Kingconn, 7USB31-F0-0029" "Kingconn, 7USB31-F0-0029" 253.29,1213.38 r270 top locked value=7USB31-F0-0029
J2 "Kingmate, S110-S-03-2-60/25/30" "2P54MM-1X3, Male" 1209.64,1120.01 r90 top value=S110-S-03-2-60/25/30
J3 "Molex, 22112032" "Molex, 22112032" 1636.35,126.7 r0 top value=22112032
J4 "Kingconn, 7USB31-F0-0029" "Kingconn, 7USB31-F0-0029" 2920.72,6048.23 r180 top locked value=7USB31-F0-0029
J5 "Kingconn, 7USB31-F0-0029" "Kingconn, 7USB31-F0-0029" 4339.2,6048.23 r180 top locked value=7USB31-F0-0029
J6 "Kingmate, S110-S-02-2-60/25/30" "2P54MM-1X2, male" 5536.71,856.9 r270 top value=S110-S-02-2-60/25/30
J7 "Kingmate, S110-S-02-2-60/25/30" "2P54MM-1X2, male" 6436.53,2661.88 r270 top value=S110-S-02-2-60/25/30
J8 "Kingmate, S110-S-02-2-60/25/30" "2P54MM-1X2, male" 6436.53,2438.86 r270 top value=S110-S-02-2-60/25/30
J9 "Kingmate, ED350V-05P" "Fixed Terminal Blocks-1X5" 6936.31,2324.11 r90 top locked value=ED350V-05P
J10 "Kingmate, S110-S-02-2-60/25/30" "2P54MM-1X2, male" 6436.53,2215.84 r270 top value=S110-S-02-2-60/25/30
J11 "Kingmate, S110-S-02-2-60/25/30" "2P54MM-1X2, male" 6436.53,1992.82 r270 top value=S110-S-02-2-60/25/30
J12 "Kingmate, S110-S-02-2-60/25/30" "2P54MM-1X2, male" 3423.44,5774.98 r270 top value=S110-S-02-2-60/25/30
J13 "Kingmate, S113-A-03-2-60/33-F0" "2P54MM-1X3, male" 4587.06,589.66 r0 top value=S113-A-03-2-60/33-F0
J14 "Kingmate, S123-T-06-2-60/33-F0" "2P54MM-2X3 Male" 2646.4,5030.7 r180 top value=S123-T-06-2-60/33-F0
J16 "Kingmate, S123-T-06-2-60/33-F0" "2P54MM-2X3 Male" 4601.95,1004.67 r0 top value=S123-T-06-2-60/33-F0
J17 "Kingmate, S110-S-05-2-60/25/30" SIP1x5_100P 3069.1,5334.01 r0 top value=S110-S-05-2-60/25/30
J18 "Kingmate, S123-T-06-2-60/33-F0" "2P54MM-2X3 Male" 3458.49,5017.64 r0 top value=S123-T-06-2-60/33-F0
J19 "Kingmate, S123-T-10-2-60/33-F0" "2P54MM-2X5 Male" 4182.59,1312.78 r270 top locked value=S123-T-10-2-60/33-F0
J20 "Kingmate, S113-A-03-2-60/33-F0" "2P54MM-1X3, male" 1087.99,2948.08 r180 top value=S113-A-03-2-60/33-F0
J21 "Kingmate, S123-T-06-2-60/33-F0" "2P54MM-2X3 Male" 5989.67,2659.58 r180 top locked value=S123-T-06-2-60/33-F0
J22 "Kingmate, S110-S-02-2-60/25/30" "2P54MM-1X2, male" 3332.34,1451.13 r0 top value=S110-S-02-2-60/25/30
J23 "Kingmate, S123-T-10-2-60/33-F0" "2P54MM-2X5 Male" 5766.32,491.62 r0 top locked value=S123-T-10-2-60/33-F0
J24 "Tag-Connect, TC2050-IDC-xx" "TC2050-FP, TAG Test Interface, Mounted" 1243.79,6054.38 r0 top locked value=TC2050-IDC-NL
J25 "Kingmate, S113-A-03-2-60/33-F0" "2P54MM-1X3, male" 3761.23,5365.61 r0 top value=S113-A-03-2-60/33-F0
J26 "Kingmate, S123-T-06-2-60/33-F0" "2P54MM-2X3 Male" 3146.55,5017.64 r0 top value=S123-T-06-2-60/33-F0
J27 "Kingmate, S110-S-02-2-60/25/30" "2P54MM-1X2, male" 3333.55,1335.29 r0 top value=S110-S-02-2-60/25/30
J28 "Kingmate, S123-T-06-2-60/33-F0" "2P54MM-2X3 Male" 3788.03,5020.18 r0 top value=S123-T-06-2-60/33-F0
J29 "Kingmate, S113-A-03-2-60/33-F0" "2P54MM-1X3, male" 2287.63,151.28 r180 top value=S113-A-03-2-60/33-F0
J30 "Kingmate, S110-S-02-2-60/25/30" "2P54MM-1X2, male" 3742.35,1416.69 r90 top value=S110-S-02-2-60/25/30
J31 "Kingmate, S110-S-02-2-60/25/30" "2P54MM-1X2, male" 1334.56,3899.05 r90 top value=S110-S-02-2-60/25/30
J32 "Kingmate, S110-S-02-2-60/25/30" "2P54MM-1X2, male" 1202.44,3899.86 r270 top value=S110-S-02-2-60/25/30
J33 "Kingmate, S123-T-10-2-60/33-F0" "2P54MM-2X5 Male" 1227.36,5507.88 r180 top value=S123-T-10-2-60/33-F0
J34 "Kingmate, S110-S-02-2-60/25/30" "2P54MM-1X2, male" 1337.86,5083.26 r90 top value=S110-S-02-2-60/25/30
J35 "Kingmate, S110-S-02-2-60/25/30" "2P54MM-1X2, male" 1178.25,5084.63 r270 top value=S110-S-02-2-60/25/30
J36 "Kingmate, S110-S-02-2-60/25/30" "2P54MM-1X2, male" 3331.53,1219.04 r0 top value=S110-S-02-2-60/25/30
J37 "Kingmate, S110-S-02-2-60/25/30" "2P54MM-1X2, male" 1641.42,1192.67 r0 top value=S110-S-02-2-60/25/30
J38 "Kingmate, S110-S-02-2-60/25/30" "2P54MM-1X2, male" 3509.5,5533.49 r0 top value=S110-S-02-2-60/25/30
J39 "Kingmate, S110-S-02-2-60/25/30" "2P54MM-1X2, male" 3887.85,1419.4 r90 top value=S110-S-02-2-60/25/30
J40 "Kingmate, S110-S-02-2-60/25/30" "2P54MM-1X2, male" 1408.44,1192.67 r180 top value=S110-S-02-2-60/25/30
J41 "Kingmate, S110-S-02-2-60/25/30" "2P54MM-1X2, male" 1406.69,1061.54 r0 top value=S110-S-02-2-60/25/30
J42 "Kingmate, S110-S-02-2-60/25/30" "2P54MM-1X2, male" 1642.8,1061.54 r180 top value=S110-S-02-2-60/25/30
J43 "Kingmate, S113-B-04-2-58/38-F0" "2P54MM-1X4, male" 1832.7,3436.59 r90 top locked value=S113-B-04-2-58/38-F0
J44 "Kingmate, S123-T-06-2-60/33-F0" "2P54MM-2X3 Male" 3005.59,1401.44 r270 top locked value=S123-T-06-2-60/33-F0
J45 "Molex, 1718561002" "2P54MM-1X2 with frction Lock" 6670.39,1031.56 r90 top value=1718561002
J46 "Molex, 1718561002" "2P54MM-1X2 with frction Lock" 2370.33,6154.06 r180 top value=1718561002
J47 "Kingmate, S110-S-02-2-60/25/30" "2P54MM-1X2, male" 2274.06,5221.96 r90 top value=S110-S-02-2-60/25/30
J48 "Molex, 1718561002" "2P54MM-1X2 with frction Lock" 6670.39,1823.98 r90 top value=1718561002
J49 "Molex, 1718561002" "2P54MM-1X2 with frction Lock" 5885.02,143.18 r0 top value=1718561002
J50 "Kingmate, S123-T-06-2-60/33-F0" "2P54MM-2X3 Male" 6861.8,5562.31 r90 top value=S123-T-06-2-60/33-F0
J51 "Kingmate, S110-S-02-2-60/25/30" "2P54MM-1X2, male" 781.5,5467.28 r180 top value=S110-S-02-2-60/25/30
J52 "Kingmate, Q110-S-02-2-38/20/30-E1" "2P0MM-1X2, male" 5094.49,4468.5 r0 top locked value=Q110-S-02-2-38/20/30-E1
J53 "Kingmate, S110-S-03-2-60/25/30" "2P54MM-1X3, Male" 6503.82,5565.2 r90 top value=S110-S-03-2-60/25/30
JMP7 "Kingmate, S901D-1-1-E1" "Sullins, QPC02SXGN-RC" 6436.53,2661.88 r90 top value="Jumper CAP open type, Pitch 2.54mm"
JMP8 "Kingmate, S901D-1-1-E1" "Sullins, QPC02SXGN-RC" 6436.53,2438.86 r90 top value="Jumper CAP open type, Pitch 2.54mm"
JMP10 "Kingmate, S901D-1-1-E1" "Sullins, QPC02SXGN-RC" 6436.53,2215.84 r90 top value="Jumper CAP open type, Pitch 2.54mm"
JMP11 "Kingmate, S901D-1-1-E1" "Sullins, QPC02SXGN-RC" 6436.53,1992.82 r90 top value="Jumper CAP open type, Pitch 2.54mm"
JMP31 "Kingmate, S901D-1-1-E1" "Sullins, QPC02SXGN-RC" 1334.56,3899.05 r90 top value="Jumper CAP open type, Pitch 2.54mm"
JMP32 "Kingmate, S901D-1-1-E1" "Sullins, QPC02SXGN-RC" 1202.44,3899.86 r90 top value="Jumper CAP open type, Pitch 2.54mm"
JMP34 "Kingmate, S901D-1-1-E1" "Sullins, QPC02SXGN-RC" 1337.86,5083.26 r90 top value="Jumper CAP open type, Pitch 2.54mm"
JMP35 "Kingmate, S901D-1-1-E1" "Sullins, QPC02SXGN-RC" 1178.25,5084.63 r90 top value="Jumper CAP open type, Pitch 2.54mm"
JMP36 "Kingmate, S901D-1-1-E1" "Sullins, QPC02SXGN-RC" 3331.53,1219.04 r0 top value="Jumper CAP open type, Pitch 2.54mm"
JMP40 "Kingmate, S901D-1-1-E1" "Sullins, QPC02SXGN-RC" 1408.44,1192.67 r180 top value="Jumper CAP open type, Pitch 2.54mm"
JMP41 "Kingmate, S901D-1-1-E1" "Sullins, QPC02SXGN-RC" 1406.69,1061.54 r180 top value="Jumper CAP open type, Pitch 2.54mm"
JMP53 "Kingmate, S901D-1-1-E1" "Sullins, QPC02SXGN-RC" 6503.82,5515.2 r90 top value="Jumper CAP open type, Pitch 2.54mm"
L1 "Maglayers, MSCDRI-7025AL-4R7M-F" "IND, 9.2x7.5mm Height 2.5mm" 2180.57,738.76 r90 top value="4.7 uH"
L2 "Maglayers, MSCDRI-7025AL-4R7M-F" "IND, 9.2x7.5mm Height 2.5mm" 2879.12,234.65 r270 top value="4.7 uH"
L3 "Maglayers, MSCDRI-7025AL-4R7M-F" "IND, 9.2x7.5mm Height 2.5mm" 2879.11,738.76 r90 top value="4.7 uH"
L4 "Wurth,  74437336022" "Wurth, 74437336022" 1136.17,1418.8 r180 top locked value=2.2uH
L5 "Wurth,  74437336022" "Wurth, 74437336022" 1556.76,1419.66 r0 top locked value=2.2uH
L6 "Maglayers, MSCDRI-7025AL-4R7M-F" "IND, 9.2x7.5mm Height 2.5mm" 1636.73,2121.11 r0 top value="4.7 uH"
L7 "Maglayers, MSCDRI-7025AL-4R7M-F" "IND, 9.2x7.5mm Height 2.5mm" 1076.76,2121.1 r180 top value="4.7 uH"
L8 "3030, 1uH, 3.3A" "IND, 3030, Height 1.2mm" 1715.8,707.96 r0 top value=1uH
L9 "Wurth,  74438336010" "Wurth, 74438336010" 1085.39,264.48 r180 top locked value=1.0uH
L10 "Murata, BLM15EG221SN1#" "FB, FB0402, RF" 3392.48,497.9 r180 top value=BLM15EG221SN1#
L11 "3225, 100uH, 150mA" "Choke , 3225, Height 2.4mm" 6278.76,2551.02 r90 top value=100uH
L12 "3225, 100uH, 150mA" "Choke , 3225, Height 2.4mm" 6273.87,2090.41 r90 top value=100uH
L13 "3030, 1uH, 3.3A" "IND, 3030, Height 1.2mm" 1478.77,4252.31 r180 top value=1uH
L14 "2016, 2.2uH, 2.2A" "IND, 2016, Height 1.0mm" 5946.32,614.85 r270 bottom value=2.2uH
LED1 "Everlight, EAST10052RA1" "Everlight, 0402, 0.25mm Height" 2051.27,1054.97 r180 top value=Red
LED2 "Kingbright, APT1608LSECK/J4-PRV" "Kingbright, LED0603, Orange" 3181.59,73.77 r0 top value=Orange
LED3 "Kingbright, APT1608LSECK/J4-PRV" "Kingbright, LED0603, Orange" 3057.8,1053.4 r0 top value=Orange
LED4 "Everlight, EAST10052RA1" "Everlight, 0402, 0.25mm Height" 1561.33,582.36 r0 top value=Red
LED5 "Kingbright, APT1608LSECK/J4-PRV" "Kingbright, LED0603, Orange" 6134.31,3034.52 r270 top value=Orange
LED8 "Kingbright, APG1608CGKC/T" "Kingbright, LED0603, Green" 2044.88,1329.43 r180 top value=Green
LED10 "Kingbright, APG1608CGKC/T" "Kingbright, LED0603, Green" 877.77,5789.49 r180 top value=Green
MH1 "Alink, N0255520A1" "PEM Standoff, M2.0, D5.5," 6908.87,3840.23 r180 top
MH2 "Mounting Hole, Hole 1.524mm, Dia 1.524mm" "Screw Hole, Hole 1.524mm, Dia 1.524mm" 2539.38,2381.89 r0 top locked
MH3 "Mounting Hole, Hole 3.2mm, Dia 6mm" "Screw Hole, Hole 3.2mm, Dia 6mm" 157.48,157.48 r180 top locked
MH4 "Mounting Hole, Hole 3.2mm, Dia 6mm" "Screw Hole, Hole 3.2mm, Dia 6mm" 157.48,6141.73 r180 top locked
MH5 "Mounting Hole, Hole 1.524mm, Dia 1.524mm" "Screw Hole, Hole 1.524mm, Dia 1.524mm" 4783.47,2381.89 r180 top locked
MH6 "Mounting Hole, Hole 3.2mm, Dia 6mm" "Screw Hole, Hole 3.2mm, Dia 6mm" 6929.15,6141.73 r0 top locked
MH7 "Mounting Hole, Hole 3.2mm, Dia 6mm" "Screw Hole, Hole 3.2mm, Dia 6mm" 6929.15,157.48 r180 top locked
MH8 "Mounting Hole, Hole 1.524mm, Dia 1.524mm" "Screw Hole, Hole 1.524mm, Dia 1.524mm" 2539.38,4035.43 r0 top locked
MH9 "Mounting Hole, Hole 3.2mm, Dia 6mm" "Screw Hole, Hole 3.2mm, Dia 6mm" 2342.53,2185.04 r0 top locked
MH10 "Mounting Hole, Hole 3.2mm, Dia 6mm" "Screw Hole, Hole 3.2mm, Dia 6mm" 4980.32,2185.04 r180 top locked
MH11 "Mounting Hole, Hole 1.524mm, Dia 1.524mm" "Screw Hole, Hole 1.524mm, Dia 1.524mm" 4783.47,4035.43 r180 top locked
MH12 "Mounting Hole, Hole 3.2mm, Dia 6mm" "Screw Hole, Hole 3.2mm, Dia 6mm" 2342.53,4232.28 r0 top locked
MH13 "Mounting Hole, Hole 3.2mm, Dia 6mm" "Screw Hole, Hole 3.2mm, Dia 6mm" 4980.32,4232.28 r180 top locked
MH14 "EMISTOP, F40M20-401126D4BM" "PEM Standoff, M2.0, D5.5, H4.0" 3661.42,4292.81 r0 top locked
MH15 "EMISTOP, F40M20-401126D4BM" "PEM Standoff, M2.0, D5.5, H4.0" 3661.42,2124.51 r0 top locked
P1 "Kingconn, 7USB31-F0-0029" "Kingconn, 7USB31-F0-0029" 3496.69,250.98 r0 top value=7USB31-F0-0029
P2 "Kingconn, 7USB31-F0-0029" "Kingconn, 7USB31-F0-0029" 3732.5,6048.23 r180 top locked value=7USB31-F0-0029
Q1 "TI, CSD17581Q3A" SON8 1357.73,259.47 r270 top locked value=CSD17581Q3A
Q2 "TI, CSD17581Q3A" SON8 1362.17,444.59 r90 top value=CSD17581Q3A
Q3 "TI, CSD17581Q3A" SON8 1362.13,809.81 r90 top value=CSD17581Q3A
Q4 "TI, CSD17581Q3A" SON8 1362.43,624.7 r270 top value=CSD17581Q3A
Q5 "SECOS, SMS2312" SOT23 867,3021.7 r0 top value=SMS2312
Q6 "SECOS, SMS2312" SOT23 796.58,3998.11 r180 top value=SMS2312
Q7 "SECOS, SMS2312" SOT23 870.95,4204.02 r0 top value=SMS2312
Q8 "SECOS, SMS2312" SOT23 798.77,5178.67 r180 top value=SMS2312
Q10 "SECOS, SMS2312" SOT23 5377,469.18 r0 bottom locked value=SMS2312
Q13 "SECOS, SMS2312" SOT23 1716.66,1787.69 r90 top value=SMS2312
Q14 "SECOS, SMS2312" SOT23 1708.91,1858.21 r270 bottom value=SMS2312
Q15 "SECOS, SMS2312" SOT23 1845.75,1858.44 r270 bottom value=SMS2312
Q16 "ON Semiconductor, FDN340P" SOT23 886.36,5889.03 r180 top value=FDN340P
Q17 "Diodes, DMG1012T-7" SOT523 1992.26,1345.04 r270 bottom value=DMG1012T-7
Q18 "Diodes, DMG1012T-7" SOT523 2089.03,1385.16 r270 bottom value=DMG1012T-7
Q19 "Diodes, DMG1012T-7" SOT523 839.59,5717.91 r0 top value=DMG1012T-7
Q20 "SECOS, SMS2312" SOT23 1573,3930.39 r180 bottom value=SMS2312
Q21 "SECOS, SMS2312" SOT23 1437.03,5295.42 r180 bottom value=SMS2312
R1 "0402, 0 Ohm" "RES, R0402, RF" 2361.28,712.1 r180 top value=0
R2 "0402, 2.2k, 5%" "RES, R0402, RF" 2068.96,1006.63 r90 top value=2.2k
R3 "0402, 36.5k, 1%" "RES, R0402, RF" 2502.13,741.2 r0 top value=36.5k
R4 "0402, 4.99k, 1%" "RES, R0402, RF" 2495.67,650.96 r90 top value=4.99k
R5 "0402, 0 Ohm" "RES, R0402, RF" 2671.56,267.31 r0 top value=0
R6 "0402, 10k, 1%" "RES, R0402, RF" 2451.53,651.1 r90 top value=10.0k
R7 "0402, 10k, 1%" "RES, R0402, RF" 2586.89,323.19 r270 top value=10.0k
R8 "0402, 22.6k, 1%" "RES, R0402, RF" 2539.38,263.86 r0 top value=22.6k
R9 "0402, 4.99k, 1%" "RES, R0402, RF" 2544.17,322.99 r270 top value=4.99k
R10 "0402, 2.2k, 5%" "RES, R0402, RF" 3096.71,87.9 r270 top value=2.2k
R11 "0402, 10k, 1%" "RES, R0402, RF" 2613.94,651.02 r90 top value=10.0k
R12 "0402, 0 Ohm" "RES, R0402, RF" 2698.63,712.9 r0 top value=0
R13 "0402, 100, 5%" "RES, R0402, RF" 2962.28,1053.37 r0 top value=100
R14 "0402, 20k, 1%" "RES, R0402, RF" 2560.44,707.87 r0 top value=20k
R15 "0402, 10k, 1%" "RES, R0402, RF" 2567.58,651.26 r90 top value=10.0k
R16 "0201, 0 Ohm" "RES, R0201, Height 0.23mm" 2462.44,329.91 r90 top value=0
R17 "0201, 0 Ohm" "RES, R0201, Height 0.23mm" 2488.19,329.73 r90 top value=0
R18 "0603, 0 Ohm" "RES, R0603, RF" 3156.37,338.77 r180 top value=0
R19 "0201, 12 Ohm, 5%" "RES, R0201, Height 0.23mm" 3086.57,586.99 r0 bottom value=12
R20 "0201, 4.7k, 5%" "RES, R0201, Height 0.23mm" 3304.89,601.87 r90 bottom value=4.7k
R21 "0201, 4.7k, 5%" "RES, R0201, Height 0.23mm" 2032.97,1149.42 r0 top value=4.7k
R22 "2512, 0.033, 1%" "RES, R2512, RCS" 3171.65,609.05 r270 top value=0.033
R23 "2512, 0.033, 1%" "RES, R2512, RCS" 2312.4,1199.9 r270 top value=0.033
R24 "0201, 12 Ohm, 5%" "RES, R0201, Height 0.23mm" 2188.7,1188.95 r180 top value=12
R25 "0201, 12 Ohm, 5%" "RES, R0201, Height 0.23mm" 3086.75,613.02 r0 bottom value=12
R26 "0201, 10k, 5%" "RES, R0201, Height 0.23mm" 6015.47,2897.74 r270 bottom value=10k
R27 "0201, 0 Ohm" "RES, R0201, Height 0.23mm" 1154.82,1557.76 r270 top value=0
R28 "0402, 52.3k, 1%" "RES, R0402, RF" 949.63,1554.56 r270 top value=52.3k
R29 "0201, 12 Ohm, 5%" "RES, R0201, Height 0.23mm" 2188.7,1215.01 r180 top value=12
R30 "0402, 9.76k, 1%" "RES, R0402, RF" 935.61,1599.46 r0 top value=9.76k
R31 "0201, 0 Ohm" "RES, R0201, Height 0.23mm" 1545.32,1555.75 r270 top value=0
R32 "0201, 10k, 5%" "RES, R0201, Height 0.23mm" 1172.61,1766.18 r0 top value=10k
R33 "0402, 30.9k, 1%" "RES, R0402, RF" 1743.81,1556.3 r270 top value=30.9k
R34 "0201, 10k, 5%" "RES, R0201, Height 0.23mm" 1172.46,1825.12 r0 top value=10k
R35 "0402, 9.76k, 1%" "RES, R0402, RF" 1754.71,1603.09 r180 top value=9.76k
R36 "0201, 10k, 5%" "RES, R0201, Height 0.23mm" 1172.46,1800.37 r0 top value=10k
R37 "0201, 0 Ohm" "RES, R0201, Height 0.23mm" 1431.8,1918.79 r90 top value=0
R38 "0402, 12.4k, 1%" "RES, R0402, RF" 1770.46,1939.42 r90 top value=12.4k
R39 "0402, 15k, 5%" "RES, R0402, RF" 1121.95,1654.16 r0 bottom value=15k
R40 "0402, 9.76k, 1%" "RES, R0402, RF" 1782.75,1893.59 r180 top value=9.76k
R41 "0402, 15k, 5%" "RES, R0402, RF" 1546.63,1920.44 r180 bottom value=15k
R42 "0402, 15k, 5%" "RES, R0402, RF" 1604.13,1653.4 r180 bottom value=15k
R43 "0201, 0 Ohm" "RES, R0201, Height 0.23mm" 1280.32,1918.3 r90 top value=0
R44 "0402, 21k, 1%" "RES, R0402, RF" 942.65,1938.67 r270 top value=21k
R45 "0402, 9.76k, 1%" "RES, R0402, RF" 930.23,1892.72 r0 top value=9.76k
R46 "0201, 10k, 5%" "RES, R0201, Height 0.23mm" 3410.64,788.07 r0 top value=10k
R47 "0201, 10k, 5%" "RES, R0201, Height 0.23mm" 3743.68,147.38 r180 bottom value=10k
R48 "0201, 10k, 5%" "RES, R0201, Height 0.23mm" 3294.13,5638.08 r180 top value=10k
R49 "0201, 0 Ohm" "RES, R0201, Height 0.23mm" 3768.25,84.86 r270 bottom value=0
R50 "0402, 0 Ohm" "RES, R0402, RF" 5299.67,858.85 r270 top value=0
R51 "0201, 10k, 5%" "RES, R0201, Height 0.23mm" 769.42,962.92 r90 top value=10k
R52 "0201, 0 Ohm" "RES, R0201, Height 0.23mm" 547.63,1225.34 r0 top value=0
R53 "0201, 0 Ohm" "RES, R0201, Height 0.23mm" 547.63,1200.46 r0 top value=0
R54 "0402, 3.48, 1%" "RES, R0402, RF" 496.53,1383.37 r0 top value=3.48
R55 "0201, 0 Ohm" "RES, R0201, Height 0.23mm" 816.26,1053.79 r0 top value=0
R56 "0201, 0 Ohm" "RES, R0201, Height 0.23mm" 816.26,1027.67 r0 top value=0
R57 "0201, 10k, 5%" "RES, R0201, Height 0.23mm" 816.26,1078.96 r0 top value=10k
R58 "0201, 10k, 5%" "RES, R0201, Height 0.23mm" 827.26,1205.65 r0 top value=10k
R59 "0201, 10k, 5%" "RES, R0201, Height 0.23mm" 685.88,895.73 r270 top value=10k
R60 "0201, 10k, 5%" "RES, R0201, Height 0.23mm" 647.27,895.73 r270 top value=10k
R61 "0201, 0 Ohm" "RES, R0201, Height 0.23mm" 693.66,930.68 r0 top value=0
R62 "0201, 0 Ohm" "RES, R0201, Height 0.23mm" 638.08,929.47 r180 top value=0
R63 "0201, 2.2K, 5%" "RES, R0201, Height 0.23mm" 1093.31,1214.08 r270 top value=2.2k
R64 "0201, 2.2K, 5%" "RES, R0201, Height 0.23mm" 1044.35,1213.78 r270 top value=2.2k
R65 "0603, 294, 1%" "RES, R0603, RF" 1693.8,313 r90 top value=294
R66 "0603, 294, 1%" "RES, R0603, RF" 1648.69,313.09 r90 top value=294
R67 "0402, 10k, 1%" "RES, R0402, RF" 1732.57,328.31 r270 top value=10.0k
R68 "0402, 10k, 1%" "RES, R0402, RF" 1873.13,490.8 r0 top value=10.0k
R69 "0402, 5.23k, 1%" "RES, R0402, RF" 1823.14,329.16 r270 top value=5.23k
R70 "0402, 56k, 1%" "RES, R0402, RF" 1856.79,329.28 r270 top value=56k
R71 "0402, 30.1k, 1%" "RES, R0402, RF" 1778.41,340.94 r0 top value=30.1k
R72 "0402, 100k, 1%" "RES, R0402, RF" 1872.91,384.59 r0 top value=100k
R73 "0603, 100 Ohm, 1%" "RES, R0603, RF" 1889.63,426.04 r0 top value=100
R74 "0201, 6.04k, 1%" "RES, R0201, Height 0.23mm" 1866.48,463.38 r0 top value=6.04k
R75 "0402, 2.2k, 5%" "RES, R0402, RF" 1497.04,582.36 r0 top value=2.2k
R76 "0201, 0 Ohm" "RES, R0201, Height 0.23mm" 1234.69,3300.28 r0 top value=0
R77 "0201, 0 Ohm" "RES, R0201, Height 0.23mm" 1217.59,3663.4 r0 top value=0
